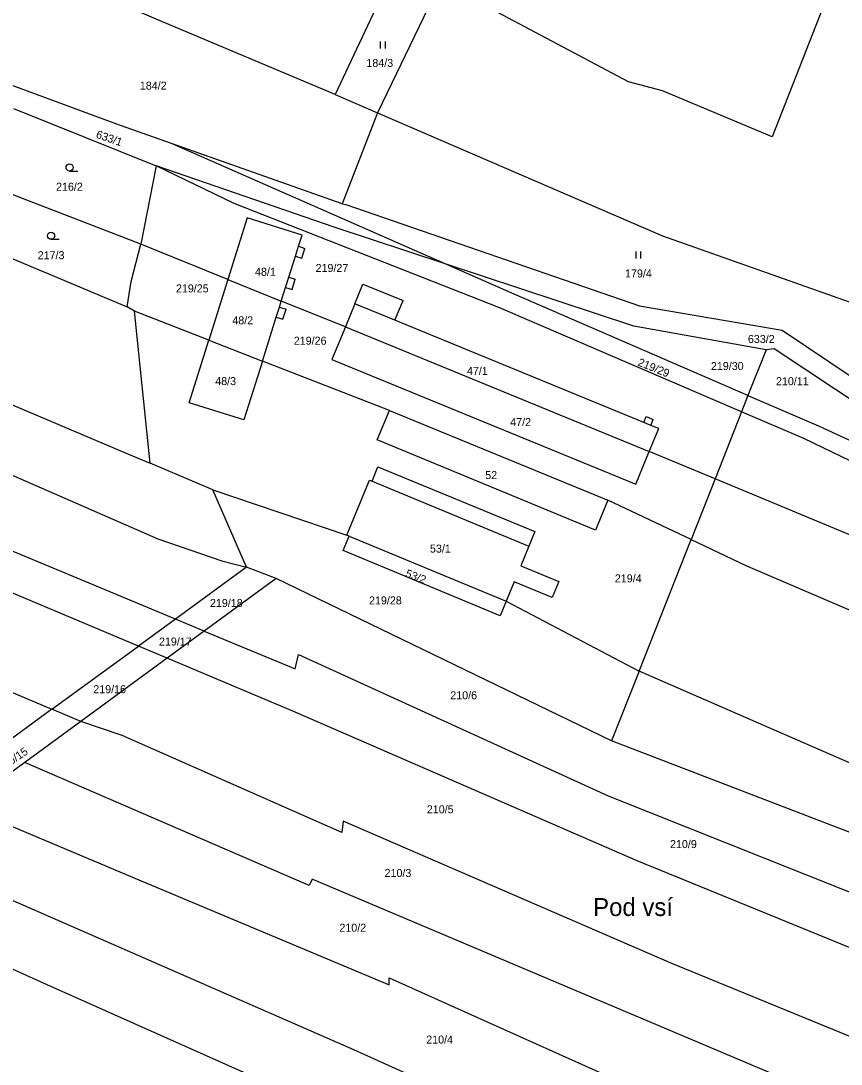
# Model space of a CAD drawing. Extents: x -746176 to -739709, y -1128407 to -1124482.
# Drawn here: x -742917.8 to -742743.6, y -1127796.2 to -1127574.6 of the extents above; entities that cross this region are included whole.
import ezdxf

# ---------------------------------------------------------------- set-up
doc = ezdxf.new("R2010")
doc.units = 0
for name, color, linetype in [('Hranice parcel', 7, 'Continuous'), ('Parcelní čísla', 7, 'Continuous'), ('Pop  PČ popisy', 7, 'Continuous'), ('Vnitřní kresba', 7, 'Continuous'), ('Značky kultur', 7, 'Continuous')]:
    doc.layers.add(name, color=color, linetype=linetype)

msp = doc.modelspace()

# ---------------------------------------------------------------- linework, layer by layer
at = {"layer": 'Hranice parcel'}
for p, q in [((-742839.05, -1127564.77), (-742851.05, -1127590.28)), ((-742829.14, -1127567.37), (-742842.01, -1127594.12)), ((-742851.05, -1127590.28), (-742842.01, -1127594.12)), ((-742919.33, -1127593.19), (-742889.07, -1127605.41)), ((-742842.01, -1127594.12), (-742849.54, -1127613.47)), ((-742827.7, -1127626.22), (-742885.79, -1127600.64)), ((-742849.54, -1127613.47), (-742885.79, -1127600.64)), ((-742889.07, -1127605.41), (-742892.31, -1127622.04)), ((-742892.31, -1127622.04), (-742925.74, -1127609.17)), ((-742873.81, -1127629.53), (-742892.31, -1127622.04)), ((-742873.81, -1127629.53), (-742877.87, -1127642.45)), ((-742873.81, -1127629.53), (-742862.47, -1127634.12)), ((-742893.68, -1127636.29), (-742895.2, -1127635.33)), ((-742848.87, -1127639.63), (-742862.47, -1127634.12)), ((-742890.34, -1127668.53), (-742893.68, -1127636.29)), ((-742877.87, -1127642.45), (-742893.68, -1127636.29)), ((-742848.87, -1127639.63), (-742784.35, -1127666.12)), ((-742877.87, -1127642.45), (-742866.48, -1127646.88)), ((-742759.53, -1127644.48), (-742763.36, -1127654.17)), ((-742839.52, -1127657.38), (-742866.48, -1127646.88)), ((-742763.36, -1127654.17), (-742764.73, -1127657.63)), ((-742839.52, -1127657.38), (-742793.13, -1127676.4)), ((-742764.73, -1127657.63), (-742770.35, -1127671.87)), ((-742770.35, -1127671.87), (-742784.35, -1127666.12)), ((-742877.02, -1127674.2), (-742890.34, -1127668.53)), ((-742770.35, -1127671.87), (-742775.45, -1127684.77)), ((-742877.02, -1127674.2), (-742848.58, -1127683.87)), ((-742869.86, -1127690.69), (-742877.02, -1127674.2)), ((-742775.45, -1127684.77), (-742793.13, -1127676.4)), ((-742848.05, -1127684.09), (-742848.58, -1127683.87)), ((-742848.05, -1127684.09), (-742814.73, -1127697.87)), ((-742786.49, -1127712.73), (-742775.45, -1127684.77)), ((-742869.86, -1127690.69), (-742884.93, -1127701.69)), ((-742863.54, -1127693.04), (-742869.86, -1127690.69)), ((-742863.54, -1127693.04), (-742878.82, -1127704.23)), ((-742792.35, -1127727.57), (-742863.54, -1127693.04)), ((-742814.73, -1127697.87), (-742786.49, -1127712.73)), ((-742962.09, -1127699.23), (-742911.19, -1127720.85)), ((-742884.93, -1127701.69), (-742892.82, -1127707.45)), ((-742878.82, -1127704.23), (-742884.93, -1127701.69)), ((-742878.82, -1127704.23), (-742886.72, -1127710.02)), ((-742911.19, -1127720.85), (-742892.82, -1127707.45)), ((-742886.72, -1127710.02), (-742892.82, -1127707.45)), ((-742886.72, -1127710.02), (-742905.07, -1127723.45)), ((-742786.49, -1127712.73), (-742792.35, -1127727.57)), ((-742911.19, -1127720.85), (-742935.96, -1127738.92)), ((-742905.07, -1127723.45), (-742911.19, -1127720.85)), ((-742905.07, -1127723.45), (-742916.95, -1127732.14)), ((-742663.65, -1127776.96), (-742792.35, -1127727.57)), ((-742916.95, -1127732.14), (-742929.76, -1127741.52))]:
    msp.add_line(p, q, dxfattribs=at)
for points in [[(-742743.76, -1127562.35), (-742758.22, -1127599.23), (-742781.54, -1127589.48), (-742788.73, -1127587.57), (-742823.54, -1127569.02), (-742829.14, -1127567.37)], [(-742851.05, -1127590.28), (-742889.01, -1127574.21), (-742909.93, -1127565.28)], [(-742885.79, -1127600.64), (-742896.8, -1127596.74), (-742927.53, -1127585.44)], [(-742842.01, -1127594.12), (-742781.53, -1127620.27), (-742738.25, -1127635.58), (-742671.97, -1127665.27), (-742626.86, -1127683.46)], [(-742764.73, -1127657.63), (-742816.28, -1127635.5), (-742872.48, -1127613.38), (-742889.07, -1127605.41)], [(-742827.7, -1127626.22), (-742851.21, -1127618.45), (-742889.07, -1127605.41)], [(-742849.54, -1127613.47), (-742848.76, -1127613.6), (-742786.4, -1127635.17), (-742756.11, -1127640.29), (-742704.21, -1127675.14), (-742663.56, -1127694.46), (-742647.49, -1127700.26), (-742632.48, -1127703.04)], [(-742862.47, -1127634.12), (-742861.56, -1127631.22), (-742860.87, -1127629.02), (-742859.48, -1127624.6), (-742858.82, -1127622.5), (-742858.07, -1127620.11), (-742869.71, -1127616.46), (-742873.81, -1127629.53)], [(-742933.59, -1127619.25), (-742932.84, -1127619.53), (-742895.2, -1127635.33)], [(-742895.2, -1127635.33), (-742894.34, -1127629.94), (-742892.31, -1127622.04)], [(-742759.53, -1127644.48), (-742787.62, -1127639.47), (-742827.7, -1127626.22)], [(-742763.36, -1127654.17), (-742813.01, -1127632.69), (-742827.7, -1127626.22)], [(-742966.93, -1127635.29), (-742957.86, -1127639.93), (-742940.86, -1127647.2), (-742894.92, -1127666.66), (-742890.34, -1127668.53)], [(-742866.48, -1127646.88), (-742863.54, -1127637.53), (-742862.87, -1127635.39), (-742862.47, -1127634.12)], [(-742784.35, -1127666.12), (-742782.33, -1127661.21), (-742783.99, -1127660.53), (-742785.47, -1127659.92), (-742838.33, -1127638.19), (-742846.84, -1127634.7), (-742848.87, -1127639.63)], [(-742989.43, -1127637.82), (-742962.79, -1127651.94), (-742947.37, -1127659.01), (-742888.66, -1127684.65), (-742875.08, -1127689.31), (-742869.86, -1127690.69)], [(-742848.87, -1127639.63), (-742851.71, -1127646.54), (-742787.2, -1127673.06), (-742784.35, -1127666.12)], [(-742866.48, -1127646.88), (-742870.4, -1127659.37), (-742882.04, -1127655.72), (-742877.87, -1127642.45)], [(-742664.42, -1127698.33), (-742705.7, -1127678.8), (-742757.77, -1127644.27), (-742759.53, -1127644.48)], [(-742884.93, -1127701.69), (-742931.01, -1127682.52), (-742982.33, -1127658.51), (-742997.69, -1127649.67)], [(-742763.36, -1127654.17), (-742748.4, -1127660.64), (-742692.32, -1127686.56), (-742664.42, -1127698.33)], [(-742892.82, -1127707.45), (-742959.07, -1127679.57), (-742986.2, -1127666.67), (-743003.07, -1127657.38)], [(-742793.13, -1127676.4), (-742795.78, -1127682.8), (-742842.1, -1127663.63), (-742839.52, -1127657.38)], [(-742640.13, -1127711.82), (-742707.48, -1127684.6), (-742751.48, -1127663.32), (-742764.73, -1127657.63)], [(-742848.58, -1127683.87), (-742843.74, -1127672.16), (-742843.19, -1127672.39), (-742841.94, -1127669.37), (-742808.61, -1127683.09), (-742809.88, -1127686.17), (-742811.62, -1127690.36), (-742803.55, -1127693.7), (-742804.94, -1127697.11), (-742813.02, -1127693.76), (-742814.73, -1127697.87)], [(-742643.36, -1127725.63), (-742711.98, -1127696.17), (-742770.35, -1127671.87)], [(-742814.73, -1127697.87), (-742816.01, -1127700.98), (-742849.31, -1127687.14), (-742848.05, -1127684.09)], [(-742775.45, -1127684.77), (-742763.82, -1127690.28), (-742650.2, -1127739.03)], [(-742878.82, -1127704.23), (-742859.56, -1127712.24), (-742858.85, -1127709.24), (-742793.05, -1127739.22), (-742667.79, -1127789.16)], [(-742691.75, -1127791.9), (-742786.9, -1127753.03), (-742859.54, -1127721.45), (-742886.72, -1127710.02)], [(-742659.43, -1127765.34), (-742739.02, -1127733.43), (-742786.49, -1127712.73)], [(-742697.57, -1127810.08), (-742723.74, -1127797.75), (-742779.52, -1127774.85), (-742849.36, -1127744.61), (-742849.6, -1127747), (-742896.29, -1127726.42), (-742905.07, -1127723.45)], [(-742705.33, -1127822.31), (-742752.11, -1127800.85), (-742855.88, -1127756.96), (-742856.57, -1127758.28), (-742916.95, -1127732.14)], [(-742929.76, -1127741.52), (-742892.25, -1127757.26), (-742839.56, -1127779.37), (-742839.56, -1127777.92), (-742777.16, -1127805.95), (-742712.92, -1127837.01)], [(-742942.9, -1127751.14), (-742921.78, -1127760.46), (-742847.12, -1127793.15), (-742812.02, -1127809), (-742724.3, -1127849.19), (-742701.43, -1127856.81), (-742666.84, -1127871.89)], [(-742670.28, -1127883.77), (-742733.59, -1127858.01), (-742796.71, -1127830.89), (-742912.22, -1127779.41), (-742955.04, -1127760.03)]]:
    msp.add_lwpolyline(points, dxfattribs=at)
at = {"layer": 'Vnitřní kresba'}
for p, q in [((-742858.82, -1127622.5), (-742857.45, -1127622.93)), ((-742859.48, -1127624.6), (-742858.11, -1127625.03)), ((-742858.11, -1127625.03), (-742857.45, -1127622.93)), ((-742860.87, -1127629.02), (-742859.49, -1127629.46)), ((-742861.56, -1127631.22), (-742860.18, -1127631.65)), ((-742860.18, -1127631.65), (-742859.49, -1127629.46)), ((-742846.84, -1127634.7), (-742845.14, -1127630.56)), ((-742845.14, -1127630.56), (-742836.62, -1127634.03)), ((-742862.87, -1127635.39), (-742861.43, -1127635.84)), ((-742862.11, -1127637.97), (-742861.43, -1127635.84)), ((-742838.33, -1127638.19), (-742836.62, -1127634.03)), ((-742863.54, -1127637.53), (-742862.11, -1127637.97)), ((-742785.47, -1127659.92), (-742784.96, -1127658.67)), ((-742784.96, -1127658.67), (-742783.48, -1127659.28)), ((-742783.99, -1127660.53), (-742783.48, -1127659.28)), ((-742843.19, -1127672.39), (-742809.88, -1127686.17))]:
    msp.add_line(p, q, dxfattribs=at)
at = {"layer": 'Značky kultur'}
for p, q in [((-742841.37, -1127580.49), (-742841.37, -1127578.99)), ((-742840.37, -1127580.49), (-742840.37, -1127578.99)), ((-742907.43, -1127606.5), (-742905.68, -1127606.5)), ((-742911.36, -1127621.01), (-742909.61, -1127621.01)), ((-742787.11, -1127625.1), (-742787.11, -1127623.6)), ((-742786.11, -1127625.1), (-742786.11, -1127623.6))]:
    msp.add_line(p, q, dxfattribs=at)
for centre in [(-742907.43, -1127605.75), (-742911.36, -1127620.26)]:
    msp.add_circle(centre, 0.75, dxfattribs=at)

# ---------------------------------------------------------------- texts
at = {"layer": 'Parcelní čísla'}
for s, p in [('184/3', (-742844.4, -1127584.39)), ('184/2', (-742892.51, -1127589.21)), ('216/2', (-742910.31, -1127610.69)), ('217/3', (-742914.21, -1127625.23)), ('48/1', (-742868.05, -1127628.76)), ('219/27', (-742855.19, -1127627.95)), ('179/4', (-742789.47, -1127629.11)), ('219/25', (-742884.85, -1127632.29)), ('48/2', (-742872.87, -1127639.07)), ('219/26', (-742859.82, -1127643.4)), ('633/2', (-742763.38, -1127643.03)), ('47/1', (-742823.05, -1127649.81)), ('219/30', (-742771.24, -1127648.78)), ('48/3', (-742876.5, -1127651.98)), ('210/11', (-742757.42, -1127652)), ('47/2', (-742813.86, -1127660.68)), ('52', (-742819.16, -1127671.94)), ('53/1', (-742830.9, -1127687.56)), ('219/4', (-742791.64, -1127693.89)), ('219/18', (-742877.62, -1127699.12)), ('219/28', (-742843.84, -1127698.57)), ('219/17', (-742888.45, -1127707.31)), ('219/16', (-742902.4, -1127717.43)), ('210/6', (-742826.59, -1127718.72)), ('210/5', (-742831.56, -1127742.95)), ('210/9', (-742779.92, -1127750.33)), ('210/3', (-742840.54, -1127756.47)), ('210/2', (-742850.13, -1127768.1)), ('210/4', (-742831.69, -1127791.86))]:
    msp.add_text(s, height=1.7, dxfattribs=at).set_placement(p)
for s, rotation, p in [('633/1', 341, (-742901.96, -1127599.4)), ('219/29', 338, (-742786.91, -1127647.77)), ('53/2', 339, (-742836.26, -1127692.63)), ('219/15', 34, (-742921.86, -1127734.11))]:
    msp.add_text(s, height=1.7, rotation=rotation, dxfattribs=at).set_placement(p)
at = {"layer": 'Pop  PČ popisy'}
msp.add_text('Pod vsí', height=3.8, dxfattribs=at).set_placement((-742796.24, -1127764.76))

doc.saveas('drawing.dxf')
